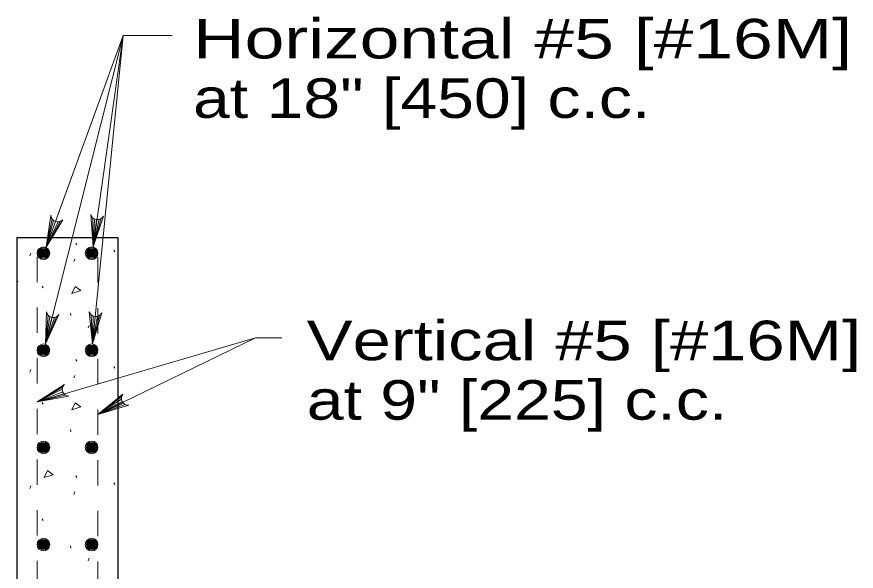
# Model space of a CAD drawing. Extents: x 1083.1 to 1117.1, y 697.4 to 743.4.
# Drawn here: x 1103.182 to 1106.491, y 726.421 to 728.608 of the extents above; entities that cross this region are included whole.
import ezdxf

# ---------------------------------------------------------------- set-up
doc = ezdxf.new("R2010")
doc.units = 0
doc.header["$LTSCALE"] = 0.064
doc.linetypes.add('SHORT_DASHED', pattern=[2.7, 1.5, -1.2])
doc.layers.add('1', color=7, linetype='Continuous', lineweight=13)

msp = doc.modelspace()

# ---------------------------------------------------------------- linework, layer by layer
at = {"layer": '1'}
for p, q in [((1103.29458, 727.31725), (1103.60158, 728.53375)), ((1103.47967, 727.318), (1103.60158, 728.53375)), ((1103.48283, 727.7005), (1103.60158, 728.53375)), ((1103.321, 727.81067), (1103.297, 727.699)), ((1103.32708, 727.80433), (1103.297, 727.699)), ((1103.33408, 727.80042), (1103.297, 727.699)), ((1103.35275, 727.80042), (1103.297, 727.699)), ((1103.34425, 727.79883), (1103.297, 727.699)), ((1103.48117, 727.81483), (1103.48333, 727.70058)), ((1103.5145, 727.81208), (1103.48333, 727.70058)), ((1103.4885, 727.81008), (1103.48333, 727.70058)), ((1103.50667, 727.80867), (1103.48333, 727.70058)), ((1103.49642, 727.80792), (1103.48333, 727.70058)), ((1103.4145, 727.7155), (1103.419, 727.70883)), ((1103.23308, 727.66558), (1103.2375, 727.67558)), ((1103.26492, 727.66442), (1103.26933, 727.66742)), ((1103.564, 727.68733), (1103.56842, 727.68067)), ((1103.40617, 727.64242), (1103.41058, 727.65242)), ((1103.18283, 727.56233), (1103.18733, 727.56533)), ((1103.28192, 727.54592), (1103.28633, 727.53925)), ((1103.394, 727.43942), (1103.39517, 727.42942)), ((1103.47508, 727.43208), (1103.47967, 727.318)), ((1103.30525, 727.43083), (1103.29458, 727.31725)), ((1103.31208, 727.42533), (1103.29458, 727.31725)), ((1103.33792, 727.42458), (1103.29458, 727.31725)), ((1103.31967, 727.42233), (1103.29458, 727.31725)), ((1103.32992, 727.42217), (1103.29458, 727.31725)), ((1103.50833, 727.43017), (1103.47967, 727.318)), ((1103.4825, 727.42758), (1103.47967, 727.318)), ((1103.50058, 727.42658), (1103.47967, 727.318)), ((1103.49033, 727.42567), (1103.47967, 727.318)), ((1103.46325, 727.38058), (1103.46767, 727.39058)), ((1103.26192, 727.08875), (1104.12308, 727.34125)), ((1103.28725, 727.28175), (1103.29167, 727.28467)), ((1103.4145, 727.25633), (1103.419, 727.24975)), ((1103.23308, 727.20642), (1103.2375, 727.21642)), ((1103.564, 727.22817), (1103.56842, 727.2215)), ((1103.40617, 727.18325), (1103.41058, 727.19325)), ((1103.36208, 727.14675), (1103.26192, 727.08875)), ((1103.36075, 727.1385), (1103.26192, 727.08875)), ((1103.36267, 727.12817), (1103.26192, 727.08875)), ((1103.36658, 727.12125), (1103.26192, 727.08875)), ((1103.373, 727.11517), (1103.26192, 727.08875)), ((1103.59458, 727.10825), (1103.50183, 727.03883)), ((1103.28192, 727.08675), (1103.28633, 727.08008)), ((1103.59417, 727.09975), (1103.50183, 727.03883)), ((1103.59717, 727.08983), (1103.50183, 727.03883)), ((1103.60192, 727.08333), (1103.50183, 727.03883)), ((1103.60917, 727.07817), (1103.50183, 727.03883)), ((1103.394, 726.98025), (1103.39517, 726.97025)), ((1103.46325, 726.92142), (1103.46767, 726.93142)), ((1103.28725, 726.89858), (1103.29167, 726.9015)), ((1103.4145, 726.79725), (1103.419, 726.79058)), ((1103.23308, 726.74725), (1103.2375, 726.75725)), ((1103.564, 726.769), (1103.56842, 726.76233)), ((1103.40617, 726.72408), (1103.41058, 726.73408)), ((1103.28192, 726.62758), (1103.28633, 726.62092)), ((1103.394, 726.52117), (1103.39517, 726.51117)), ((1103.46325, 726.46225), (1103.46767, 726.47225))]:
    msp.add_line(p, q, dxfattribs=at)
at = {"layer": '1', "lineweight": 25}
msp.add_line((1103.582, 727.73592), (1103.18175, 727.736), dxfattribs=at)
at = {"layer": '1', "linetype": 'SHORT_DASHED'}
for p, q in [((1103.262, 725.56125), (1103.26217, 727.6815)), ((1103.50183, 724.95925), (1103.50183, 727.66992))]:
    msp.add_line(p, q, dxfattribs=at)
at = {"layer": '1'}
for points in [[(1103.297, 727.699), (1103.60158, 728.53375), (1103.795, 728.53375)], [(1103.36333, 727.80758), (1103.297, 727.699), (1103.31642, 727.82483)], [(1103.52317, 727.82175), (1103.48333, 727.70058), (1103.47358, 727.82758)], [(1103.34767, 727.433), (1103.29458, 727.31725), (1103.29908, 727.44458)], [(1103.51692, 727.43983), (1103.47967, 727.318), (1103.46708, 727.44475)], [(1103.50183, 727.03892), (1104.12308, 727.34125), (1104.22692, 727.34125)], [(1103.36925, 727.15767), (1103.26192, 727.08875), (1103.38733, 727.11108)], [(1103.60017, 727.11975), (1103.50183, 727.03883), (1103.62375, 727.07575)]]:
    msp.add_lwpolyline(points, dxfattribs=at)
at = {"layer": '1', "lineweight": 25}
for points in [[(1103.18175, 727.736), (1103.18175, 727.54658), (1103.18175, 727.29658), (1103.18175, 726.48833), (1103.18175, 725.38092)], [(1103.582, 725.38217), (1103.582, 727.02233), (1103.582, 727.73592)]]:
    msp.add_lwpolyline(points, dxfattribs=at)
at = {"layer": '1'}
for points in [[(1103.39833, 727.51708), (1103.41167, 727.54475), (1103.43392, 727.52817)], [(1103.39833, 727.05792), (1103.41167, 727.08567), (1103.43392, 727.069)], [(1103.2895, 726.79042), (1103.30283, 726.81817), (1103.32508, 726.8015)]]:
    msp.add_lwpolyline(points, close=True, dxfattribs=at)
for centre, major_axis, start_param, end_param in [((1103.34339, 727.82579), (-0.02127, -0.01658), 5.655204, 8.0258171), ((1103.49961, 727.83469), (-0.01445, -0.02277), 5.5424008, 7.913014), ((1103.32578, 727.44862), (-0.01133, 0.02447), 1.2902344, 3.6608475), ((1103.49294, 727.45239), (-0.01344, 0.02338), 1.33579, 3.7064032), ((1103.38773, 727.13803), (0.02635, -0.00571), 2.5430293, 4.9136424), ((1103.62099, 727.10252), (0.02697, 0), 2.4468029, 4.8174161)]:
    msp.add_ellipse(centre, major_axis=major_axis, ratio=0.999895, start_param=start_param, end_param=end_param, dxfattribs=at)
for centre, major_axis in [((1103.28697, 727.67555), (0.02499, 0)), ((1103.28697, 727.67555), (0.02499, 0)), ((1103.47688, 727.67555), (0.02499, 0)), ((1103.47688, 727.67555), (0.02499, 0)), ((1103.28697, 727.67555), (0.02077, 0)), ((1103.28697, 727.67555), (0.01726, 0)), ((1103.28697, 727.67555), (0.01434, 0)), ((1103.28697, 727.67555), (0.01192, 0)), ((1103.28697, 727.67555), (0.0099, 0)), ((1103.28697, 727.67555), (0.00823, 0)), ((1103.28697, 727.67555), (0.00684, 0)), ((1103.28697, 727.67555), (0.00568, 0)), ((1103.28697, 727.67555), (0.00472, 0)), ((1103.28697, 727.67555), (0.00392, 0)), ((1103.28697, 727.67555), (0.00326, 0)), ((1103.28697, 727.67555), (0.00271, 0)), ((1103.28697, 727.67555), (0.00225, 0)), ((1103.28697, 727.67555), (0.00187, 0)), ((1103.47688, 727.67555), (0.02077, 0)), ((1103.47688, 727.67555), (0.01726, 0)), ((1103.47688, 727.67555), (0.01434, 0)), ((1103.47688, 727.67555), (0.01192, 0)), ((1103.47688, 727.67555), (0.0099, 0)), ((1103.47688, 727.67555), (0.00823, 0)), ((1103.47688, 727.67555), (0.00684, 0)), ((1103.47688, 727.67555), (0.00568, 0)), ((1103.47688, 727.67555), (0.00472, 0)), ((1103.47688, 727.67555), (0.00392, 0)), ((1103.47688, 727.67555), (0.00326, 0)), ((1103.47688, 727.67555), (0.00271, 0)), ((1103.47688, 727.67555), (0.00225, 0)), ((1103.47688, 727.67555), (0.00187, 0)), ((1103.28697, 727.29235), (0.02499, 0)), ((1103.28697, 727.29235), (0.02499, 0)), ((1103.28697, 727.29235), (0.02077, 0)), ((1103.28697, 727.29235), (0.01726, 0)), ((1103.28697, 727.29235), (0.01434, 0)), ((1103.28697, 727.29235), (0.01192, 0)), ((1103.28697, 727.29235), (0.0099, 0)), ((1103.28697, 727.29235), (0.00823, 0)), ((1103.47688, 727.29235), (0.02499, 0)), ((1103.47688, 727.29235), (0.02499, 0)), ((1103.47688, 727.29235), (0.02077, 0)), ((1103.47688, 727.29235), (0.01726, 0)), ((1103.47688, 727.29235), (0.01434, 0)), ((1103.47688, 727.29235), (0.01192, 0)), ((1103.47688, 727.29235), (0.0099, 0)), ((1103.47688, 727.29235), (0.00823, 0)), ((1103.28697, 727.29235), (0.00684, 0)), ((1103.28697, 727.29235), (0.00568, 0)), ((1103.28697, 727.29235), (0.00472, 0)), ((1103.28697, 727.29235), (0.00392, 0)), ((1103.28697, 727.29235), (0.00326, 0)), ((1103.28697, 727.29235), (0.00271, 0)), ((1103.28697, 727.29235), (0.00225, 0)), ((1103.28697, 727.29235), (0.00187, 0)), ((1103.47688, 727.29235), (0.00684, 0)), ((1103.47688, 727.29235), (0.00568, 0)), ((1103.47688, 727.29235), (0.00472, 0)), ((1103.47688, 727.29235), (0.00392, 0)), ((1103.47688, 727.29235), (0.00326, 0)), ((1103.47688, 727.29235), (0.00271, 0)), ((1103.47688, 727.29235), (0.00225, 0)), ((1103.47688, 727.29235), (0.00187, 0)), ((1103.28697, 726.90916), (0.02499, 0)), ((1103.28697, 726.90916), (0.02499, 0)), ((1103.28697, 726.90916), (0.02077, 0)), ((1103.28697, 726.90916), (0.01726, 0)), ((1103.28697, 726.90916), (0.01434, 0)), ((1103.28697, 726.90916), (0.01192, 0)), ((1103.28697, 726.90916), (0.0099, 0)), ((1103.28697, 726.90916), (0.00823, 0)), ((1103.28697, 726.90916), (0.00684, 0)), ((1103.28697, 726.90916), (0.00568, 0)), ((1103.28697, 726.90916), (0.00472, 0)), ((1103.28697, 726.90916), (0.00392, 0)), ((1103.28697, 726.90916), (0.00326, 0)), ((1103.28697, 726.90916), (0.00271, 0)), ((1103.28697, 726.90916), (0.00225, 0)), ((1103.28697, 726.90916), (0.00187, 0)), ((1103.47688, 726.90916), (0.02499, 0)), ((1103.47688, 726.90916), (0.02499, 0)), ((1103.47688, 726.90916), (0.02077, 0)), ((1103.47688, 726.90916), (0.01726, 0)), ((1103.47688, 726.90916), (0.01434, 0)), ((1103.47688, 726.90916), (0.01192, 0)), ((1103.47688, 726.90916), (0.0099, 0)), ((1103.47688, 726.90916), (0.00823, 0)), ((1103.47688, 726.90916), (0.00684, 0)), ((1103.47688, 726.90916), (0.00568, 0)), ((1103.47688, 726.90916), (0.00472, 0)), ((1103.47688, 726.90916), (0.00392, 0)), ((1103.47688, 726.90916), (0.00326, 0)), ((1103.47688, 726.90916), (0.00271, 0)), ((1103.47688, 726.90916), (0.00225, 0)), ((1103.47688, 726.90916), (0.00187, 0)), ((1103.28697, 726.52596), (0.02499, 0)), ((1103.28697, 726.52596), (0.02499, 0)), ((1103.28697, 726.52596), (0.02077, 0)), ((1103.28697, 726.52596), (0.01726, 0)), ((1103.28697, 726.52596), (0.01434, 0)), ((1103.47688, 726.52596), (0.02499, 0)), ((1103.47688, 726.52596), (0.02499, 0)), ((1103.47688, 726.52596), (0.02077, 0)), ((1103.47688, 726.52596), (0.01726, 0)), ((1103.47688, 726.52596), (0.01434, 0)), ((1103.28697, 726.52596), (0.01192, 0)), ((1103.28697, 726.52596), (0.0099, 0)), ((1103.28697, 726.52596), (0.00823, 0)), ((1103.28697, 726.52596), (0.00684, 0)), ((1103.28697, 726.52596), (0.00568, 0)), ((1103.28697, 726.52596), (0.00472, 0)), ((1103.28697, 726.52596), (0.00392, 0)), ((1103.28697, 726.52596), (0.00326, 0)), ((1103.28697, 726.52596), (0.00271, 0)), ((1103.28697, 726.52596), (0.00225, 0)), ((1103.28697, 726.52596), (0.00187, 0)), ((1103.47688, 726.52596), (0.01192, 0)), ((1103.47688, 726.52596), (0.0099, 0)), ((1103.47688, 726.52596), (0.00823, 0)), ((1103.47688, 726.52596), (0.00684, 0)), ((1103.47688, 726.52596), (0.00568, 0)), ((1103.47688, 726.52596), (0.00472, 0)), ((1103.47688, 726.52596), (0.00392, 0)), ((1103.47688, 726.52596), (0.00326, 0)), ((1103.47688, 726.52596), (0.00271, 0)), ((1103.47688, 726.52596), (0.00225, 0)), ((1103.47688, 726.52596), (0.00187, 0))]:
    msp.add_ellipse(centre, major_axis=major_axis, ratio=0.999895, dxfattribs=at)

# ---------------------------------------------------------------- texts
for s, width, p in [('Horizontal #5 [#16M]', 1.35, (1103.87658, 728.44392)), ('at 18" [450] c.c.', 1.25, (1103.87658, 728.20925)), ('Vertical #5 [#16M]', 1.3, (1104.32492, 727.25325)), ('at 9" [225] c.c.', 1.25, (1104.32492, 727.01858))]:
    msp.add_text(s, height=0.156, dxfattribs=dict(at, width=width)).set_placement(p)

doc.saveas('drawing.dxf')
